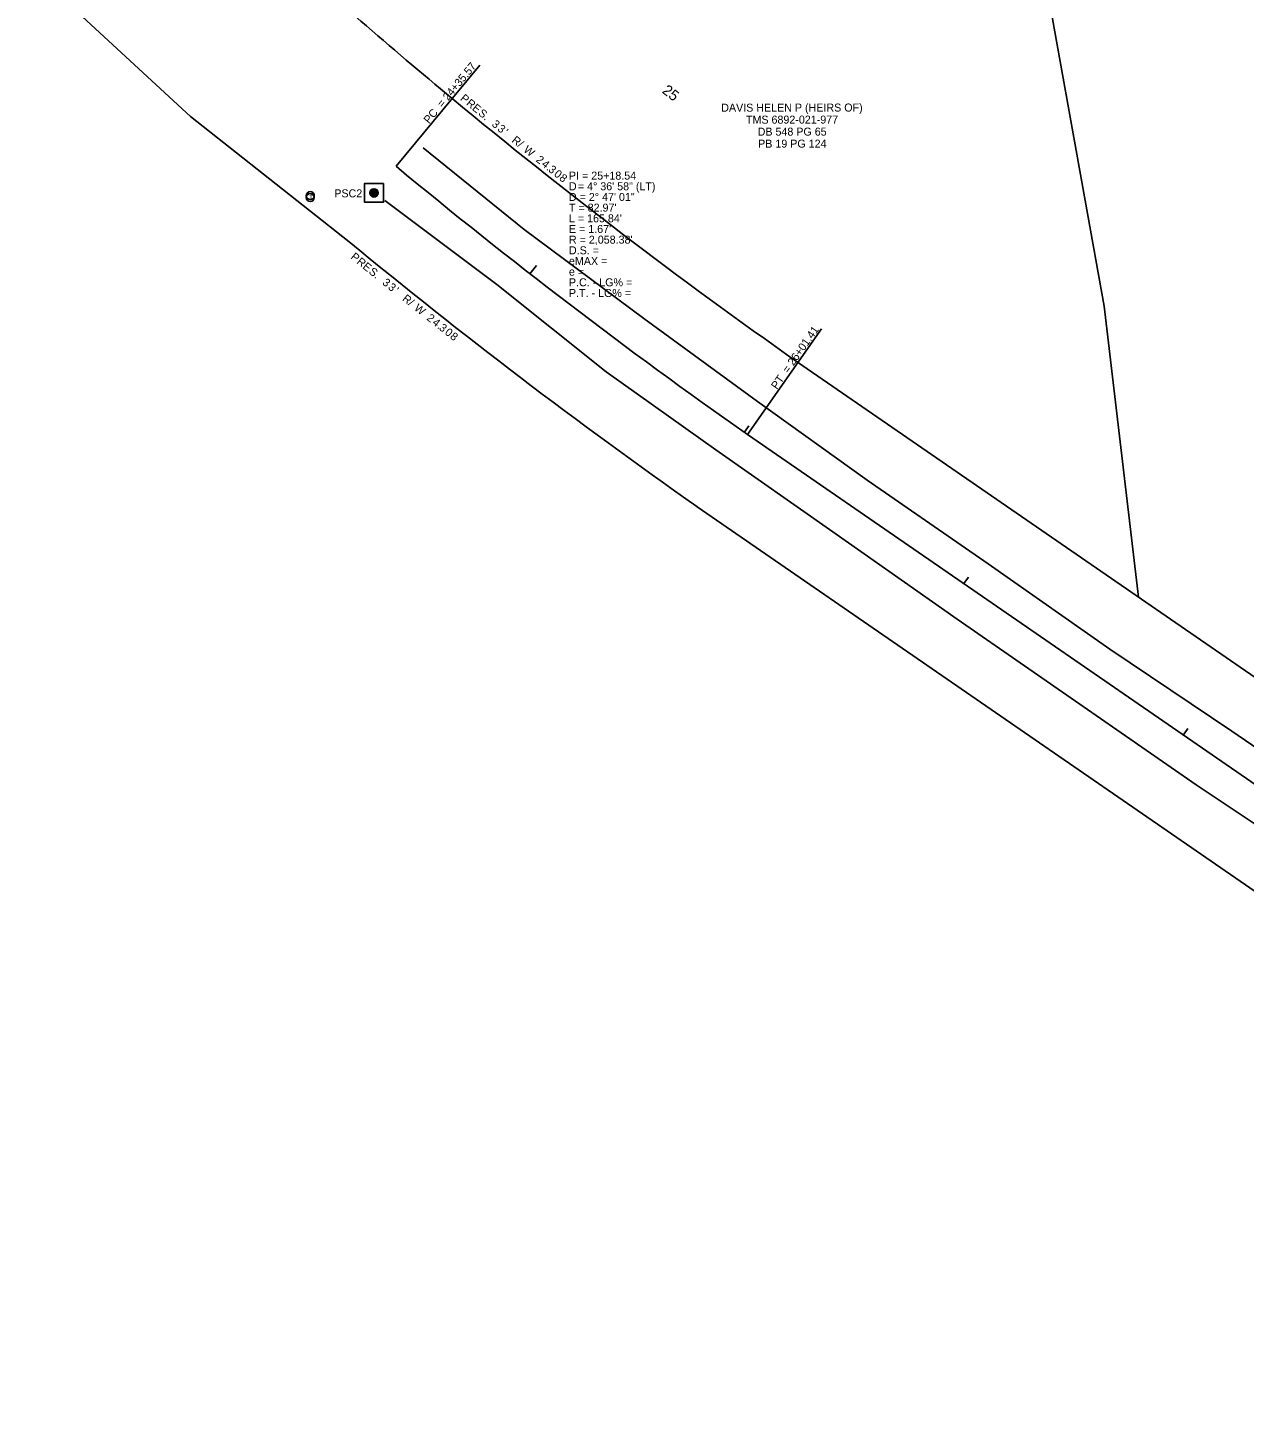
# Model space of a CAD drawing. Extents: x 1687085 to 1692731, y 826429 to 830660.
# Drawn here: x 1689932 to 1690388, y 829297 to 829818 of the extents above; entities that cross this region are included whole.
import ezdxf

# ---------------------------------------------------------------- set-up
doc = ezdxf.new("R2010")
doc.units = 0
for name, color, linetype in [('RD_EX_Bridge', 7, 'Continuous'), ('RD_EX_DV_Prop', 7, 'Continuous'), ('RD_EX_DV_TX_Prop', 7, 'Continuous'), ('RD_EX_Road', 7, 'Continuous'), ('RD_EX_RW', 7, 'Continuous'), ('RD_EX_RW_TX', 7, 'Continuous'), ('RD_EX_UT', 7, 'Continuous'), ('RD_HC_Cl', 7, 'Continuous'), ('RD_HC_Data', 7, 'Continuous'), ('RD_HC_Data_Tic', 7, 'Continuous'), ('RD_HC_Survey', 7, 'Continuous'), ('RD_HC_Survey_txCode', 7, 'Continuous'), ('RD_HC_TX_Sta20', 7, 'Continuous')]:
    doc.layers.add(name, color=color, linetype=linetype)

msp = doc.modelspace()

# ---------------------------------------------------------------- linework, layer by layer
at = {"layer": 'RD_EX_Bridge'}
msp.add_line((1690737.18, 829296.63), (1690201.95, 829665.46), dxfattribs=at)
msp.add_arc((1691383.53, 831350.92), 2058.38, 230.35157, 234.96781, dxfattribs=at)
at = {"layer": 'RD_EX_DV_Prop'}
for p, q in [((1689932.01, 829841.02), (1689993.1, 829784.63)), ((1689993.1, 829784.63), (1690052.56, 829737.73))]:
    msp.add_line(p, q, dxfattribs=at)
msp.add_lwpolyline([(1690273.09, 830061.9), (1690335.8, 829713.5), (1690348.62, 829604.47)], dxfattribs=at)
msp.add_arc((1691383.53, 831350.92), 2025.38, 227.81175, 230.35157, dxfattribs=at)
at = {"layer": 'RD_EX_Road'}
for points in [[(1690426.27, 829525.1), (1690383.68, 829554.25), (1690337.92, 829584.95), (1690292.19, 829616.91), (1690246.85, 829648.26), (1690205.73, 829677.81), (1690163.14, 829708.97), (1690118.21, 829742.28), (1690080.34, 829772.89)], [(1690413.37, 829505.39), (1690370.29, 829534.15), (1690323.35, 829566.62), (1690280.6, 829596.2), (1690234.01, 829628.92), (1690190.12, 829659.7), (1690148.91, 829688.89), (1690107.96, 829721.65), (1690065.96, 829753.19)]]:
    msp.add_lwpolyline(points, dxfattribs=at)
at = {"layer": 'RD_EX_RW'}
msp.add_line((1690483.01, 829511.86), (1690220.78, 829692.56), dxfattribs=at)
msp.add_lwpolyline([(1690445.56, 829457.51), (1690183.12, 829638.36), (1690183.01, 829638.44)], dxfattribs=at)
for radius, start, end in [(2025.38, 230.35157, 234.96407), (2091.38, 230.47543, 234.96781)]:
    msp.add_arc((1691383.53, 831350.92), radius, start, end, dxfattribs=at)
at = {"layer": 'RD_EX_UT'}
for centre in [(1690037.98, 829754.29), (1690037.99, 829755.02)]:
    msp.add_circle(centre, 1.5, dxfattribs=at)
at = {"layer": 'RD_HC_Cl'}
msp.add_line((1690201.95, 829665.46), (1690737.18, 829296.63), dxfattribs=at)
msp.add_arc((1691383.53, 831350.92), 2058.38, 230.35157, 234.96781, dxfattribs=at)
at = {"layer": 'RD_HC_Data'}
for p, q in [((1690070.13, 829766.02), (1690101.57, 829803.96)), ((1690201.95, 829665.46), (1690229.7, 829705.05))]:
    msp.add_line(p, q, dxfattribs=at)
at = {"layer": 'RD_HC_Data_Tic'}
for p, q in [((1690120.38, 829725.69), (1690122.83, 829728.85)), ((1690200.8, 829666.27), (1690202.52, 829668.73)), ((1690283.13, 829609.52), (1690284.83, 829611.99)), ((1690365.47, 829552.78), (1690367.18, 829555.25))]:
    msp.add_line(p, q, dxfattribs=at)
at = {"layer": 'RD_HC_Survey'}
for p, q in [((1690060.74, 829754.95), (1690060.74, 829757.12)), ((1690060.79, 829754.9), (1690060.79, 829757.17)), ((1690060.84, 829754.85), (1690060.84, 829757.21)), ((1690060.89, 829754.81), (1690060.89, 829757.25)), ((1690060.94, 829754.77), (1690060.94, 829757.29)), ((1690060.99, 829754.74), (1690060.99, 829757.33)), ((1690061.04, 829754.71), (1690061.04, 829757.36)), ((1690061.09, 829754.68), (1690061.09, 829757.39)), ((1690061.14, 829754.65), (1690061.14, 829757.41)), ((1690061.19, 829754.63), (1690061.19, 829757.44)), ((1690061.24, 829754.6), (1690061.24, 829757.46)), ((1690061.29, 829754.58), (1690061.29, 829757.48)), ((1690061.34, 829754.56), (1690061.34, 829757.5)), ((1690061.39, 829754.55), (1690061.39, 829757.52)), ((1690061.44, 829754.53), (1690061.44, 829757.53)), ((1690061.49, 829754.52), (1690061.49, 829757.54)), ((1690061.54, 829754.51), (1690061.54, 829757.55)), ((1690061.59, 829754.5), (1690061.59, 829757.56)), ((1690061.64, 829754.49), (1690061.64, 829757.57)), ((1690061.69, 829754.49), (1690061.69, 829757.58)), ((1690061.74, 829754.48), (1690061.74, 829757.58)), ((1690061.79, 829754.48), (1690061.79, 829757.59)), ((1690061.84, 829754.48), (1690061.84, 829757.59)), ((1690061.89, 829754.48), (1690061.89, 829757.59)), ((1690061.94, 829754.48), (1690061.94, 829757.58)), ((1690061.99, 829754.48), (1690061.99, 829757.58)), ((1690062.04, 829754.49), (1690062.04, 829757.58)), ((1690062.09, 829754.5), (1690062.09, 829757.57)), ((1690062.14, 829754.5), (1690062.14, 829757.56)), ((1690062.19, 829754.51), (1690062.19, 829757.55)), ((1690062.24, 829754.53), (1690062.24, 829757.54)), ((1690062.29, 829754.54), (1690062.29, 829757.52)), ((1690062.34, 829754.56), (1690062.34, 829757.51)), ((1690062.39, 829754.57), (1690062.39, 829757.49)), ((1690062.44, 829754.59), (1690062.44, 829757.47)), ((1690062.49, 829754.61), (1690062.49, 829757.45)), ((1690062.54, 829754.64), (1690062.54, 829757.43)), ((1690062.59, 829754.66), (1690062.59, 829757.4)), ((1690062.64, 829754.69), (1690062.64, 829757.37)), ((1690062.69, 829754.72), (1690062.69, 829757.34)), ((1690062.74, 829754.76), (1690062.74, 829757.31)), ((1690062.79, 829754.79), (1690062.79, 829757.27)), ((1690062.84, 829754.83), (1690062.84, 829757.23)), ((1690062.89, 829754.87), (1690062.89, 829757.19)), ((1690062.94, 829754.92), (1690062.94, 829757.14)), ((1690062.99, 829754.97), (1690062.99, 829757.09)), ((1690060.34, 829755.67), (1690060.34, 829756.39)), ((1690060.39, 829755.5), (1690060.39, 829756.56)), ((1690060.44, 829755.38), (1690060.44, 829756.68)), ((1690060.49, 829755.28), (1690060.49, 829756.78)), ((1690060.54, 829755.2), (1690060.54, 829756.87)), ((1690060.59, 829755.12), (1690060.59, 829756.94)), ((1690060.64, 829755.06), (1690060.64, 829757.01)), ((1690060.69, 829755), (1690060.69, 829757.06)), ((1690063.04, 829755.03), (1690063.04, 829757.03)), ((1690063.09, 829755.09), (1690063.09, 829756.97)), ((1690063.14, 829755.16), (1690063.14, 829756.9)), ((1690063.19, 829755.24), (1690063.19, 829756.82)), ((1690063.24, 829755.33), (1690063.24, 829756.73)), ((1690063.29, 829755.44), (1690063.29, 829756.62)), ((1690063.34, 829755.58), (1690063.34, 829756.48)), ((1690063.39, 829755.81), (1690063.39, 829756.26))]:
    msp.add_line(p, q, dxfattribs=at)
msp.add_lwpolyline([(1690065.39, 829759.57), (1690058.32, 829759.57), (1690058.32, 829752.5), (1690065.39, 829752.5)], close=True, dxfattribs=at)
msp.add_circle((1690061.85, 829756.03), 1.55, dxfattribs=at)

# ---------------------------------------------------------------- texts
at = {"layer": 'RD_EX_DV_TX_Prop'}
for s, p in [('DAVIS HELEN P (HEIRS OF)', (1690192.12, 829786.47)), ('TMS 6892-021-977', (1690201.4, 829781.98)), ('DB 548 PG 65', (1690205.79, 829777.48)), ('PB 19 PG 124', (1690205.97, 829772.98))]:
    msp.add_text(s, height=3, rotation=0.0605, dxfattribs=at).set_placement(p)
at = {"layer": 'RD_EX_RW_TX'}
for s, rotation, p in [('P', 320.4605, (1690094, 829791.05)), ('R', 320.5421, (1690096.23, 829789.22)), ('E', 320.6237, (1690098.45, 829787.38)), ('S', 320.708, (1690100.75, 829785.5)), ('.', 320.7856, (1690102.87, 829783.76)), ('3', 320.8932, (1690105.82, 829781.36)), ('3', 320.9708, (1690107.95, 829779.63)), ("'", 321.0484, (1690110.07, 829777.9)), ('R', 321.1654, (1690113.29, 829775.31)), ('/', 321.247, (1690115.53, 829773.5)), ('W', 321.3259, (1690117.71, 829771.75)), ('2', 321.4951, (1690122.38, 829768.02)), ('4', 321.5713, (1690124.48, 829766.35)), ('.', 321.6395, (1690126.37, 829764.85)), ('3', 321.6623, (1690127, 829764.35)), ('0', 321.7398, (1690129.15, 829762.65)), ('8', 321.8107, (1690131.12, 829761.1)), ('P', 320.6284, (1690052.9, 829731.62)), ('R', 320.7073, (1690055.14, 829729.79)), ('E', 320.7862, (1690057.37, 829727.96)), ('S', 320.8677, (1690059.68, 829726.08)), ('.', 320.9427, (1690061.81, 829724.35)), ('3', 321.0468, (1690064.77, 829721.95)), ('3', 321.1218, (1690066.9, 829720.22)), ("'", 321.1968, (1690069.04, 829718.5)), ('R', 321.31, (1690072.26, 829715.91)), ('/', 321.3889, (1690074.51, 829714.1)), ('W', 321.4652, (1690076.7, 829712.36)), ('2', 321.6288, (1690081.38, 829708.63)), ('4', 321.7025, (1690083.49, 829706.96)), ('.', 321.7685, (1690085.39, 829705.47)), ('3', 321.7905, (1690086.02, 829704.97)), ('0', 321.8655, (1690088.18, 829703.27)), ('8', 321.9341, (1690090.15, 829701.72))]:
    msp.add_text(s, height=3, rotation=rotation, dxfattribs=at).set_placement(p)
at = {"layer": 'RD_EX_UT'}
for p in [(1690037.62, 829753.48), (1690037.63, 829754.2)]:
    msp.add_text('T', height=1.5, rotation=360, dxfattribs=at).set_placement(p)
at = {"layer": 'RD_HC_Data'}
for s, rotation, p in [('PC  = 24+35.57', 50.3516, (1690082.51, 829781.74)), ('PT  = 26+01.41', 54.9678, (1690213.02, 829682.12))]:
    msp.add_text(s, height=3, rotation=rotation, dxfattribs=at).set_placement(p)
for s, p in [('PI = 25+18.54', (1690135, 829761)), ('D', (1690135, 829757)), ('   = 4%%d 36\' 58" (LT)', (1690135, 829757)), ("T = 82.97'", (1690135, 829749)), ('D = 2%%d 47\' 01"', (1690135, 829753)), ("L = 165.84'", (1690135, 829745)), ("E = 1.67'", (1690135, 829741)), ("R = 2,058.38'", (1690135, 829737)), ('eMAX = ', (1690135, 829729)), ('D.S. = ', (1690135, 829733)), ('e = ', (1690135, 829725)), ('P.C. - LG% = ', (1690135, 829721)), ('P.T. - LG% = ', (1690135, 829717))]:
    msp.add_text(s, height=3, dxfattribs=at).set_placement(p)
at = {"layer": 'RD_HC_Survey_txCode'}
msp.add_text('PSC2', height=3, dxfattribs=at).set_placement((1690046.98, 829754.36))
at = {"layer": 'RD_HC_TX_Sta20'}
msp.add_text('25', height=4, rotation=322.145, dxfattribs=at).set_placement((1690169.65, 829793.79))

doc.saveas('drawing.dxf')
